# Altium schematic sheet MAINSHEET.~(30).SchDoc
size 594 x 420 mm; Scale: 1:1; Разраб.: Иванов; Обозначение документа: АБВГ.123456.001 Э3; Пров.: Петров; Утв.: Сидоров; Наименование организации: ОАО "Концерн "МПО-Гидроприбор"; Перв. применение: АБВГ.123456.000; Наименование изделия 1: Плата; Наименование изделия 2: Схема электрическая; Наименование изделия 3: принципиальная; Нач. отд.: Нач. отд.; Фамилия нач. отд.: Сидоров
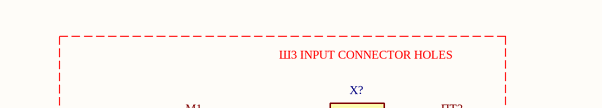
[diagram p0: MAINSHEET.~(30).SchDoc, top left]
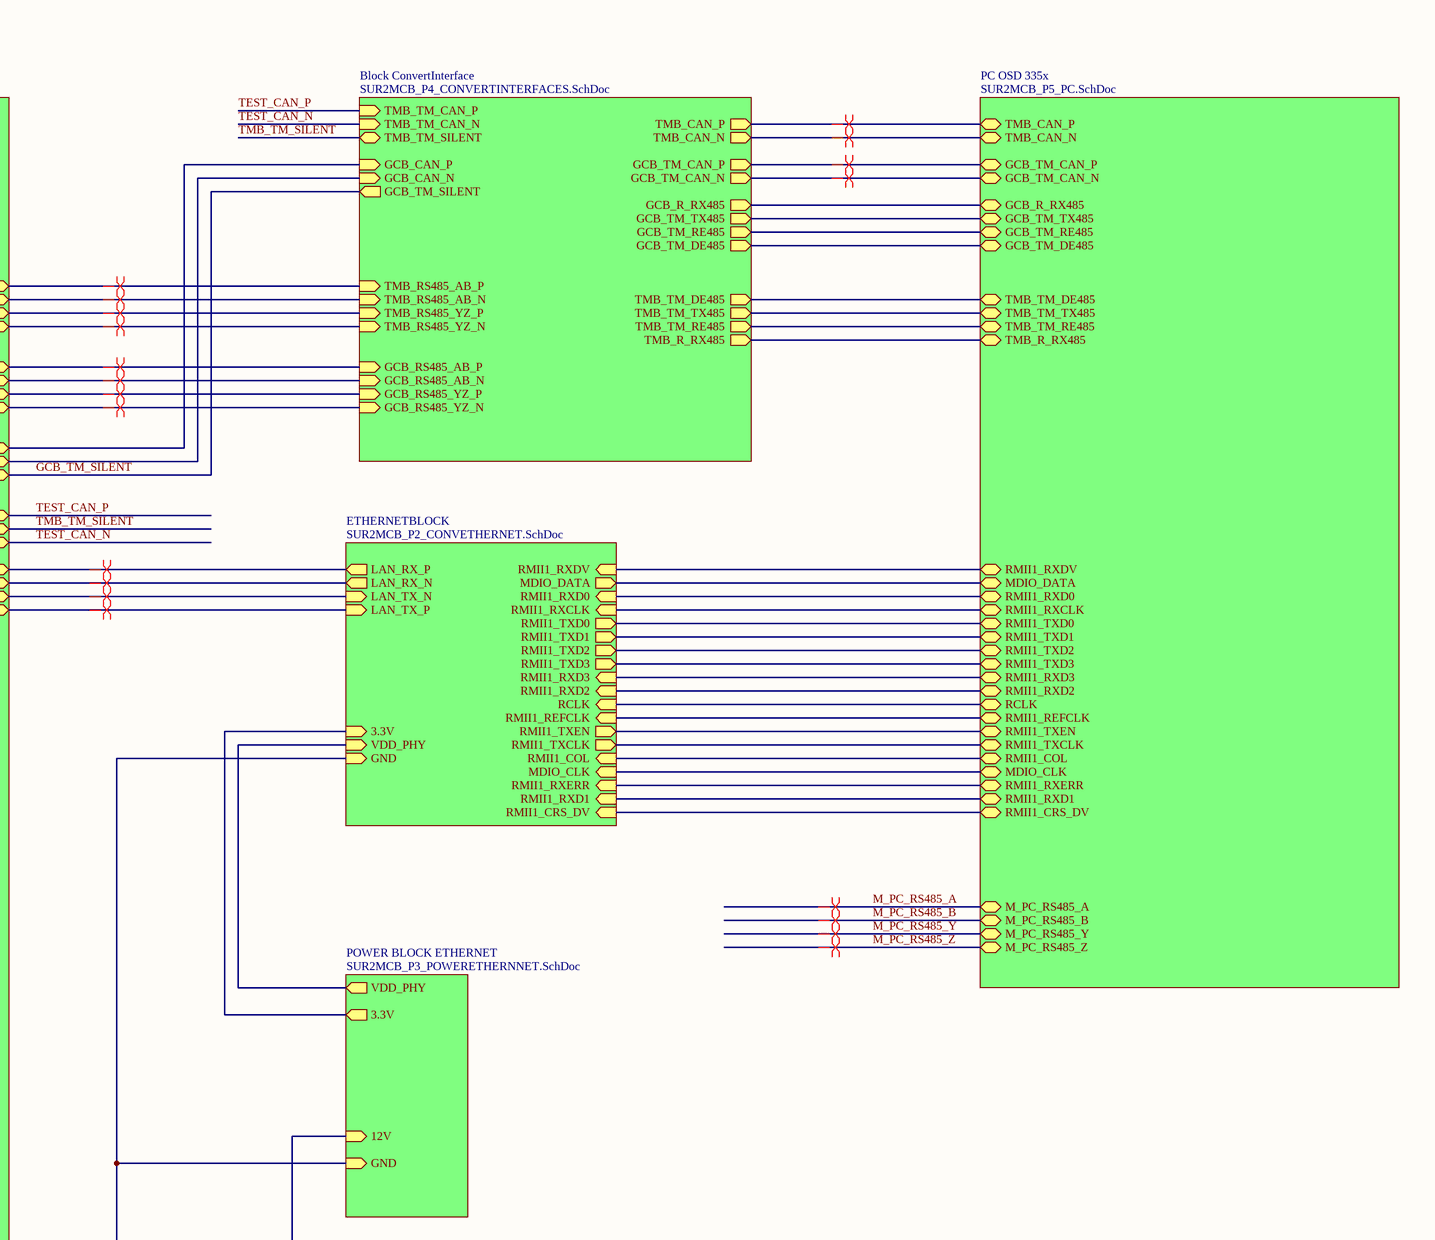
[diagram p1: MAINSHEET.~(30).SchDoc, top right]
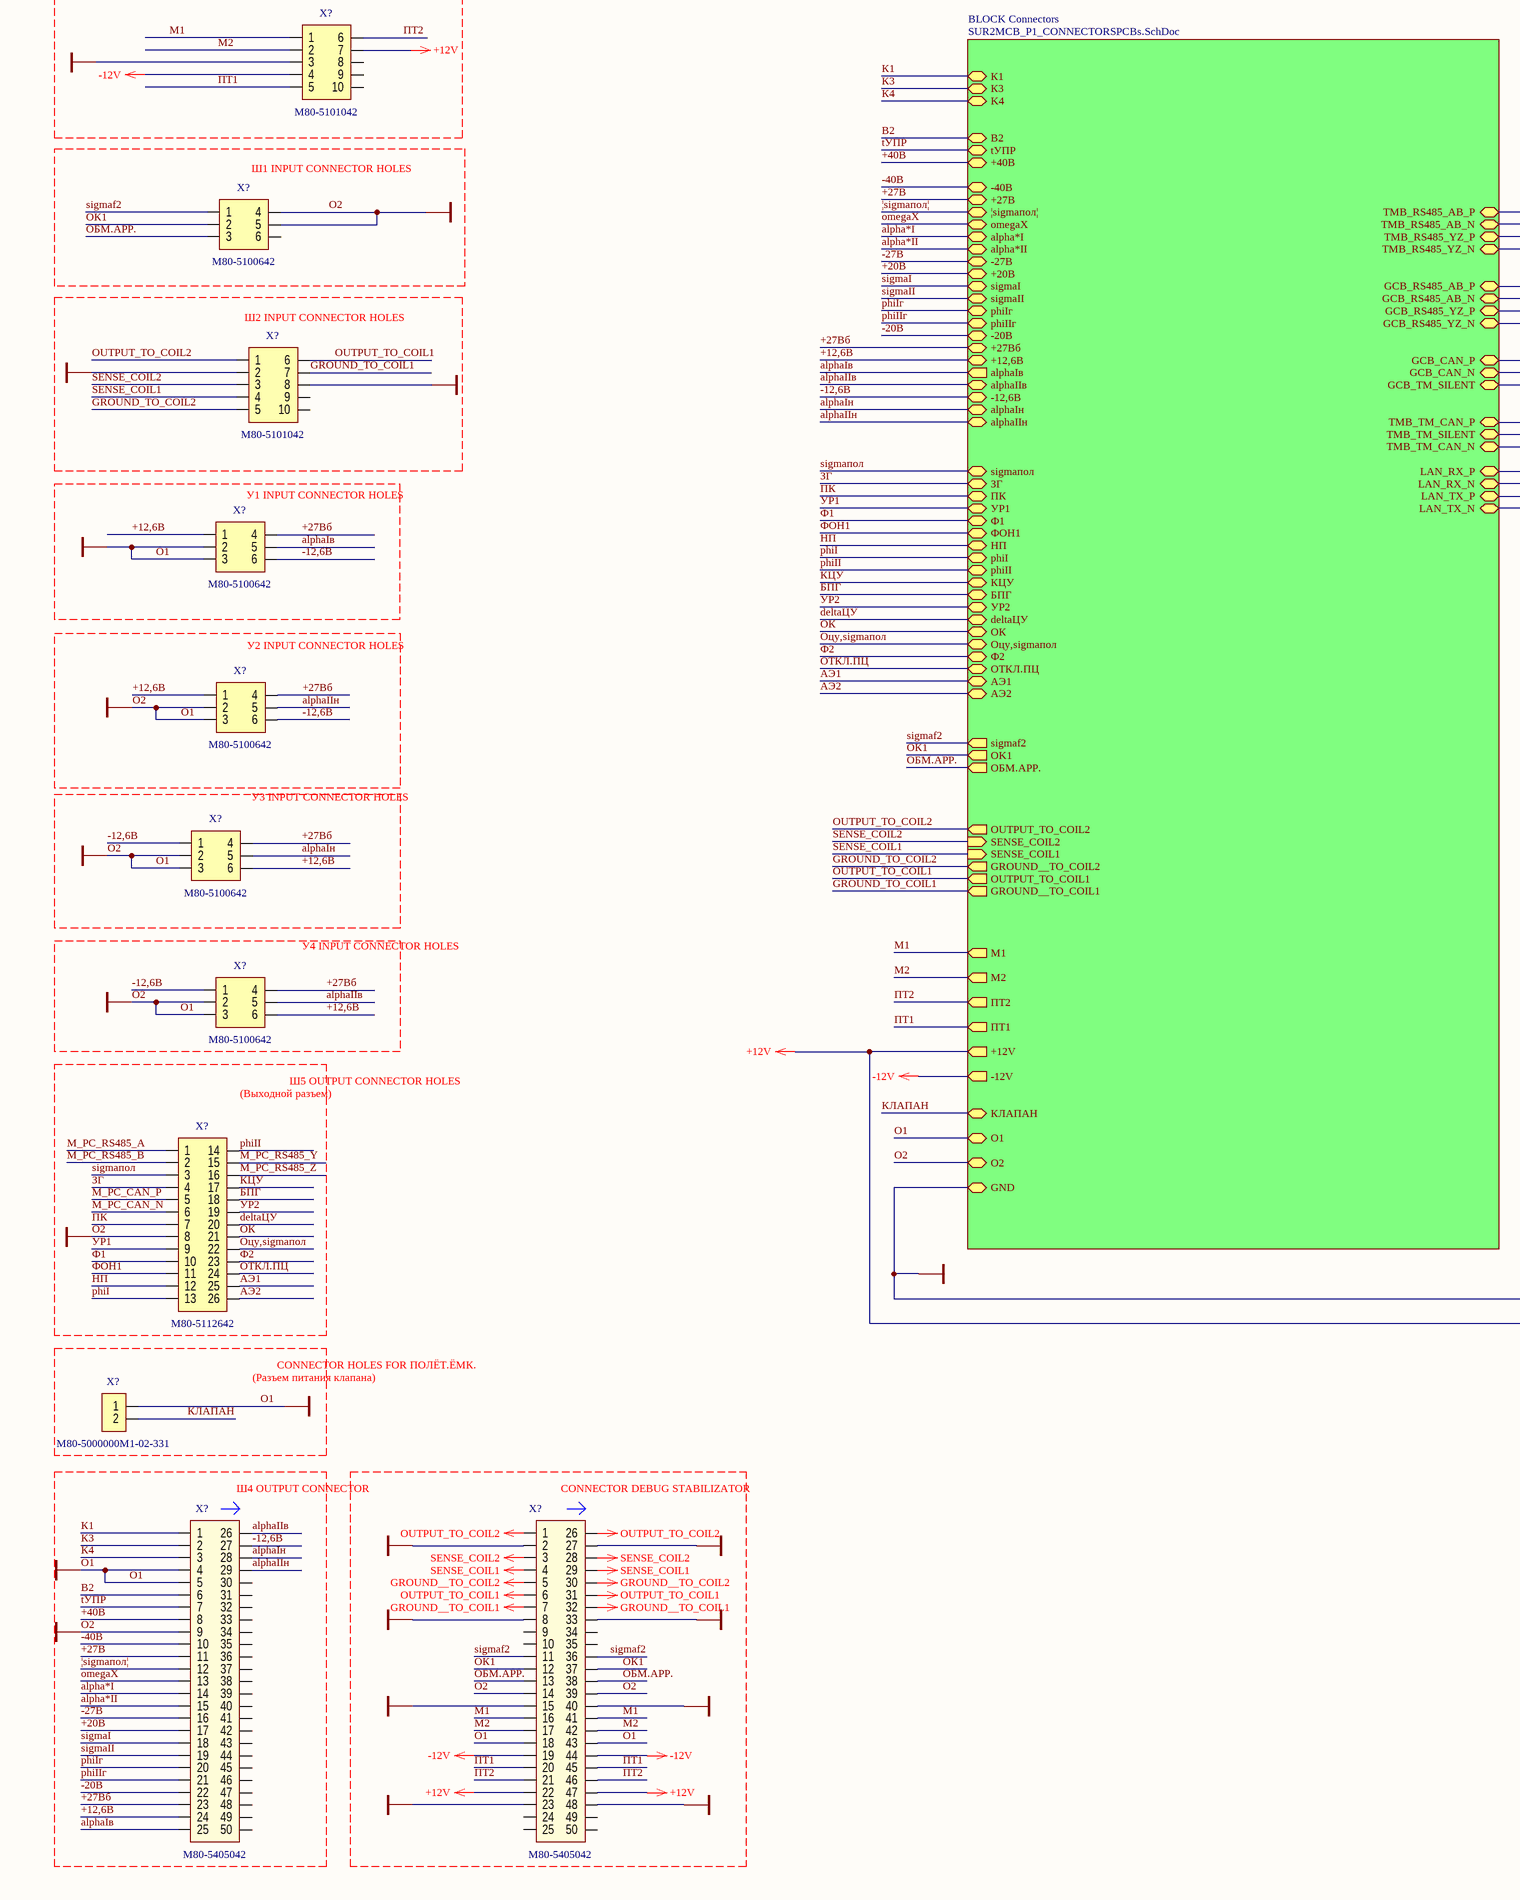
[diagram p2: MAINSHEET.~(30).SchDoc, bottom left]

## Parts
(Parts that share a designator on the sheet are numbered #1, #2 ... from top to bottom, then left to right.)
X?#1  value M80-5101042  [M80-5101042]
X?#2  value M80-5100642  [M80-5100642]
X?#3  value M80-5101042  [M80-5101042]
X?#4  value M80-5100642  [M80-5100642]
X?#5  value M80-5100642  [M80-5100642]
X?#6  value M80-5100642  [M80-5100642]
X?#7  value M80-5100642  [M80-5100642]
X?#8  value M80-5112642  [M80-5112642_HOR]
X?#9  value M80-5000000M1-02-331  [M80-5000000M1-02-331]
X?#10  value M80-5405042  [M80-5405042]
X?#11  value M80-5405042  [M80-5405042]

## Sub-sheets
BLOCK Connectors = SUR2MCB_P1_CONNECTORSPCBs.SchDoc: tУПР (bidir), B2 (bidir), K4 (bidir), +40В (bidir), К1 (bidir), К3 (bidir), OUTPUT_TO_COIL2 (out), OUTPUT_TO_COIL1 (out), GROUND__TO_COIL1 (out), SENSE_COIL2 (in), GROUND__TO_COIL2 (out), SENSE_COIL1 (in), M1 (out), КЛАПАН (bidir), О1 (bidir), O2 (bidir), TMB_RS485_AB_N (bidir), TMB_RS485_AB_P (bidir), TMB_RS485_YZ_N (bidir), TMB_RS485_YZ_P (bidir), LAN_RX_P (bidir), LAN_RX_N (bidir), LAN_TX_P (bidir), LAN_TX_N (bidir), GCB_RS485_AB_N (bidir), GCB_RS485_YZ_N (bidir), GCB_RS485_YZ_P (bidir), GCB_RS485_AB_P (bidir), GCB_CAN_P (bidir), GCB_CAN_N (bidir), GCB_TM_SILENT (bidir), TMB_TM_CAN_P (bidir), TMB_TM_SILENT (bidir), TMB_TM_CAN_N (bidir), -40В (bidir), +27В (bidir), ¦sigmaпол¦ (bidir), omegaX (bidir), alpha*II (bidir), alpha*I (bidir), -27В (bidir), +20В (bidir), -20В (bidir), sigmaII (bidir), sigmaI (bidir), phiIIг (bidir), phiIг (bidir), +27Вб (bidir), +12,6В (bidir), -12,6В (bidir), alphaIв (out), alphaIIв (bidir), alphaIIн (bidir), alphaIн (bidir), sigmaпол (bidir), ЗГ (bidir), ПК (bidir), УР1 (bidir), Ф1 (bidir), ФОН1 (bidir), НП (bidir), phiI (bidir), phiII (bidir), ПТ2 (out), +12V (out), КЦУ (bidir), БПГ (bidir), УР2 (bidir), deltaЦУ (bidir), ОК (bidir), Оцу,sigmaпол (bidir), Ф2 (bidir), ОТКЛ.ПЦ (bidir), АЭ1 (bidir), АЭ2 (bidir), ПТ1 (out), M2 (out), -12V (out), sigmaf2 (out), OK1 (out), ОБМ.АРР. (out), GND (bidir)
Block ConvertInterface = SUR2MCB_P4_CONVERTINTERFACES.SchDoc: TMB_TM_TX485 (out), GCB_RS485_YZ_P (in), TMB_R_RX485 (out), GCB_RS485_YZ_N (in), GCB_RS485_AB_P (in), TMB_TM_RE485 (out), GCB_TM_CAN_P (out), TMB_TM_DE485 (out), GCB_TM_CAN_N (out), GCB_RS485_AB_N (in), TMB_RS485_YZ_N (in), GCB_TM_RE485 (out), GCB_CAN_P (in), GCB_R_RX485 (out), GCB_TM_TX485 (out), TMB_RS485_AB_P (in), GCB_TM_SILENT (out), GCB_CAN_N (in), TMB_RS485_YZ_P (in), TMB_RS485_AB_N (in), GCB_TM_DE485 (out), TMB_TM_SILENT (bidir), TMB_TM_CAN_P (in), TMB_TM_CAN_N (in), TMB_CAN_P (out), TMB_CAN_N (out)
ETHERNETBLOCK = SUR2MCB_P2_CONVETHERNET.SchDoc: RMII1_RXDV (in), MDIO_DATA (out), RMII1_RXD0 (in), RMII1_RXCLK (in), RMII1_TXD0 (out), RMII1_TXD2 (out), RMII1_TXD3 (out), RMII1_RXD3 (in), RMII1_RXD2 (in), LAN_RX_P (out), RCLK (in), LAN_RX_N (out), LAN_TX_N (in), RMII1_REFCLK (in), RMII1_TXEN (out), LAN_TX_P (in), RMII1_TXCLK (out), RMII1_COL (in), MDIO_CLK (in), RMII1_TXD1 (out), GND (in), VDD_PHY (in), 3.3V (in), RMII1_RXERR (in), RMII1_RXD1 (in), RMII1_CRS_DV (in)
PC OSD 335x = SUR2MCB_P5_PC.SchDoc: GCB_R_RX485 (bidir), GCB_TM_CAN_N (bidir), GCB_TM_RE485 (bidir), GCB_TM_TX485 (bidir), TMB_TM_DE485 (bidir), GCB_TM_DE485 (bidir), TMB_TM_RE485 (bidir), TMB_TM_TX485 (bidir), TMB_R_RX485 (bidir), RMII1_TXCLK (bidir), GCB_TM_CAN_P (bidir), TMB_CAN_N (bidir), TMB_CAN_P (bidir), RMII1_TXD0 (bidir), RMII1_CRS_DV (bidir), RMII1_TXD2 (bidir), MDIO_CLK (bidir), RMII1_RXDV (bidir), RMII1_TXD1 (bidir), RMII1_TXEN (bidir), RMII1_RXD3 (bidir), RMII1_RXERR (bidir), RMII1_TXD3 (bidir), RMII1_RXD0 (bidir), MDIO_DATA (bidir), RMII1_RXD2 (bidir), RMII1_RXD1 (bidir), RMII1_COL (bidir), RMII1_RXCLK (bidir), RMII1_REFCLK (bidir), RCLK (bidir), M_PC_RS485_Z (bidir), M_PC_RS485_Y (bidir), M_PC_RS485_B (bidir), M_PC_RS485_A (bidir)
POWER BLOCK ETHERNET = SUR2MCB_P3_POWERETHERNNET.SchDoc: 12V (in), VDD_PHY (out), 3.3V (out), GND (in)

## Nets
+12V: X?#1.7 X?#11.22 X?#11.47 ; sheet BLOCK Connectors/+12V, sheet POWER BLOCK ETHERNET/12V
-12V: X?#1.4 X?#11.19 X?#11.44 ; sheet BLOCK Connectors/-12V
GROUND__TO_COIL1: X?#11.7 X?#11.32
GROUND__TO_COIL2: X?#11.5 X?#11.30
OUTPUT_TO_COIL1: X?#3.6 X?#11.6 X?#11.31 ; sheet BLOCK Connectors/OUTPUT_TO_COIL1
OUTPUT_TO_COIL2: X?#3.1 X?#11.1 X?#11.26 ; sheet BLOCK Connectors/OUTPUT_TO_COIL2
SENSE_COIL1: X?#3.4 X?#11.4 X?#11.29 ; sheet BLOCK Connectors/SENSE_COIL1
SENSE_COIL2: X?#3.3 X?#11.3 X?#11.28 ; sheet BLOCK Connectors/SENSE_COIL2
О1: X?#1.3 X?#2.4 X?#2.5 X?#3.2 X?#3.8 X?#4.2 X?#4.3 X?#5.2 X?#5.3 X?#6.2 X?#6.3 X?#7.2 X?#7.3 X?#8.8 X?#9.1 X?#10.4 X?#10.5 X?#10.9 X?#11.2 X?#11.8 X?#11.14 X?#11.15 X?#11.18 X?#11.23 X?#11.27 X?#11.33 X?#11.39 X?#11.40 X?#11.43 X?#11.48 ; sheet BLOCK Connectors/О1, sheet BLOCK Connectors/O2, sheet BLOCK Connectors/GND, sheet ETHERNETBLOCK/GND, sheet POWER BLOCK ETHERNET/GND  [also labelled GND, О2]
+12,6В: X?#4.1 X?#5.1 X?#6.6 X?#7.6 X?#10.24 ; sheet BLOCK Connectors/+12,6В
+20В: X?#10.17 ; sheet BLOCK Connectors/+20В
+27В: X?#10.11 ; sheet BLOCK Connectors/+27В
+27Вб: X?#4.4 X?#5.4 X?#6.4 X?#7.4 X?#10.23 ; sheet BLOCK Connectors/+27Вб
+40В: X?#10.8 ; sheet BLOCK Connectors/+40В
-12,6В: X?#4.6 X?#5.6 X?#6.1 X?#7.1 X?#10.27 ; sheet BLOCK Connectors/-12,6В
-20В: X?#10.22 ; sheet BLOCK Connectors/-20В
-27В: X?#10.16 ; sheet BLOCK Connectors/-27В
-40В: X?#10.10 ; sheet BLOCK Connectors/-40В
alpha*I: X?#10.14 ; sheet BLOCK Connectors/alpha*I
alpha*II: X?#10.15 ; sheet BLOCK Connectors/alpha*II
alphaIIв: X?#7.5 X?#10.26 ; sheet BLOCK Connectors/alphaIIв
alphaIIн: X?#5.5 X?#10.29 ; sheet BLOCK Connectors/alphaIIн
alphaIв: X?#4.5 X?#10.25 ; sheet BLOCK Connectors/alphaIв
alphaIн: X?#6.5 X?#10.28 ; sheet BLOCK Connectors/alphaIн
deltaЦУ: X?#8.20 ; sheet BLOCK Connectors/deltaЦУ
GCB_TM_SILENT: sheet BLOCK Connectors/GCB_TM_SILENT, sheet Block ConvertInterface/GCB_TM_SILENT
GROUND_TO_COIL1: X?#3.7 ; sheet BLOCK Connectors/GROUND__TO_COIL1
GROUND_TO_COIL2: X?#3.5 ; sheet BLOCK Connectors/GROUND__TO_COIL2
M_PC_CAN_N: X?#8.6
M_PC_CAN_P: X?#8.5
M_PC_RS485_A: X?#8.1 ; sheet PC OSD 335x/M_PC_RS485_A
M_PC_RS485_B: X?#8.2 ; sheet PC OSD 335x/M_PC_RS485_B
M_PC_RS485_Y: X?#8.15 ; sheet PC OSD 335x/M_PC_RS485_Y
M_PC_RS485_Z: X?#8.16 ; sheet PC OSD 335x/M_PC_RS485_Z
omegaX: X?#10.13 ; sheet BLOCK Connectors/omegaX
phiI: X?#8.13 ; sheet BLOCK Connectors/phiI
phiII: X?#8.14 ; sheet BLOCK Connectors/phiII
phiIIг: X?#10.21 ; sheet BLOCK Connectors/phiIIг
phiIг: X?#10.20 ; sheet BLOCK Connectors/phiIг
sigmaf2: X?#2.1 X?#11.11 X?#11.36 ; sheet BLOCK Connectors/sigmaf2
sigmaI: X?#10.18 ; sheet BLOCK Connectors/sigmaI
sigmaII: X?#10.19 ; sheet BLOCK Connectors/sigmaII
sigmaпол: X?#8.3 ; sheet BLOCK Connectors/sigmaпол
TEST_CAN_N: sheet BLOCK Connectors/TMB_TM_CAN_N, sheet Block ConvertInterface/TMB_TM_CAN_N
TEST_CAN_P: sheet BLOCK Connectors/TMB_TM_CAN_P, sheet Block ConvertInterface/TMB_TM_CAN_P
TMB_TM_SILENT: sheet BLOCK Connectors/TMB_TM_SILENT, sheet Block ConvertInterface/TMB_TM_SILENT
tУПР: X?#10.7 ; sheet BLOCK Connectors/tУПР
¦sigmaпол¦: X?#10.12 ; sheet BLOCK Connectors/¦sigmaпол¦
АЭ1: X?#8.25 ; sheet BLOCK Connectors/АЭ1
АЭ2: X?#8.26 ; sheet BLOCK Connectors/АЭ2
БПГ: X?#8.18 ; sheet BLOCK Connectors/БПГ
В2: X?#10.6 ; sheet BLOCK Connectors/B2
ЗГ: X?#8.4 ; sheet BLOCK Connectors/ЗГ
К1: X?#10.1 ; sheet BLOCK Connectors/К1
К3: X?#10.2 ; sheet BLOCK Connectors/К3
К4: X?#10.3 ; sheet BLOCK Connectors/K4
КЛАПАН: X?#9.2 ; sheet BLOCK Connectors/КЛАПАН
КЦУ: X?#8.17 ; sheet BLOCK Connectors/КЦУ
М1: X?#1.1 X?#11.16 X?#11.41 ; sheet BLOCK Connectors/M1
М2: X?#1.2 X?#11.17 X?#11.42 ; sheet BLOCK Connectors/M2
НП: X?#8.12 ; sheet BLOCK Connectors/НП
ОБМ.АРР.: X?#2.3 X?#11.13 X?#11.38 ; sheet BLOCK Connectors/ОБМ.АРР.
ОК: X?#8.21 ; sheet BLOCK Connectors/ОК
ОК1: X?#2.2 X?#11.12 X?#11.37 ; sheet BLOCK Connectors/OK1
ОТКЛ.ПЦ: X?#8.24 ; sheet BLOCK Connectors/ОТКЛ.ПЦ
Оцу,sigmaпол: X?#8.22 ; sheet BLOCK Connectors/Оцу,sigmaпол
ПК: X?#8.7 ; sheet BLOCK Connectors/ПК
ПТ1: X?#1.5 X?#11.20 X?#11.45 ; sheet BLOCK Connectors/ПТ1
ПТ2: X?#1.6 X?#11.21 X?#11.46 ; sheet BLOCK Connectors/ПТ2
УР1: X?#8.9 ; sheet BLOCK Connectors/УР1
УР2: X?#8.19 ; sheet BLOCK Connectors/УР2
Ф1: X?#8.10 ; sheet BLOCK Connectors/Ф1
Ф2: X?#8.23 ; sheet BLOCK Connectors/Ф2
ФОН1: X?#8.11 ; sheet BLOCK Connectors/ФОН1
(unnamed): sheet BLOCK Connectors/TMB_RS485_AB_N, sheet Block ConvertInterface/TMB_RS485_AB_N
(unnamed): sheet BLOCK Connectors/TMB_RS485_AB_P, sheet Block ConvertInterface/TMB_RS485_AB_P  [a separate net that carries the same name]
(unnamed): sheet BLOCK Connectors/TMB_RS485_YZ_N, sheet Block ConvertInterface/TMB_RS485_YZ_N  [a separate net that carries the same name]
(unnamed): sheet BLOCK Connectors/TMB_RS485_YZ_P, sheet Block ConvertInterface/TMB_RS485_YZ_P  [a separate net that carries the same name]
(unnamed): sheet BLOCK Connectors/LAN_RX_P, sheet ETHERNETBLOCK/LAN_RX_P  [a separate net that carries the same name]
(unnamed): sheet BLOCK Connectors/LAN_RX_N, sheet ETHERNETBLOCK/LAN_RX_N  [a separate net that carries the same name]
(unnamed): sheet BLOCK Connectors/LAN_TX_P, sheet ETHERNETBLOCK/LAN_TX_N  [a separate net that carries the same name]
(unnamed): sheet BLOCK Connectors/LAN_TX_N, sheet ETHERNETBLOCK/LAN_TX_P  [a separate net that carries the same name]
(unnamed): sheet BLOCK Connectors/GCB_RS485_AB_N, sheet Block ConvertInterface/GCB_RS485_AB_N  [a separate net that carries the same name]
(unnamed): sheet BLOCK Connectors/GCB_RS485_YZ_N, sheet Block ConvertInterface/GCB_RS485_YZ_N  [a separate net that carries the same name]
(unnamed): sheet BLOCK Connectors/GCB_RS485_YZ_P, sheet Block ConvertInterface/GCB_RS485_YZ_P  [a separate net that carries the same name]
(unnamed): sheet BLOCK Connectors/GCB_RS485_AB_P, sheet Block ConvertInterface/GCB_RS485_AB_P  [a separate net that carries the same name]
(unnamed): sheet BLOCK Connectors/GCB_CAN_P, sheet Block ConvertInterface/GCB_CAN_P  [a separate net that carries the same name]
(unnamed): sheet BLOCK Connectors/GCB_CAN_N, sheet Block ConvertInterface/GCB_CAN_N  [a separate net that carries the same name]
(unnamed): sheet ETHERNETBLOCK/RMII1_RXDV, sheet PC OSD 335x/RMII1_RXDV  [a separate net that carries the same name]
(unnamed): sheet ETHERNETBLOCK/MDIO_DATA, sheet PC OSD 335x/MDIO_DATA  [a separate net that carries the same name]
(unnamed): sheet ETHERNETBLOCK/RMII1_RXD0, sheet PC OSD 335x/RMII1_RXD0  [a separate net that carries the same name]
(unnamed): sheet ETHERNETBLOCK/RMII1_RXCLK, sheet PC OSD 335x/RMII1_RXCLK  [a separate net that carries the same name]
(unnamed): sheet ETHERNETBLOCK/RMII1_TXD0, sheet PC OSD 335x/RMII1_TXD0  [a separate net that carries the same name]
(unnamed): sheet ETHERNETBLOCK/RMII1_TXD2, sheet PC OSD 335x/RMII1_TXD2  [a separate net that carries the same name]
(unnamed): sheet ETHERNETBLOCK/RMII1_TXD3, sheet PC OSD 335x/RMII1_TXD3  [a separate net that carries the same name]
(unnamed): sheet ETHERNETBLOCK/RMII1_RXD3, sheet PC OSD 335x/RMII1_RXD3  [a separate net that carries the same name]
(unnamed): sheet ETHERNETBLOCK/RMII1_RXD2, sheet PC OSD 335x/RMII1_RXD2  [a separate net that carries the same name]
(unnamed): sheet ETHERNETBLOCK/RCLK, sheet PC OSD 335x/RCLK  [a separate net that carries the same name]
(unnamed): sheet ETHERNETBLOCK/RMII1_REFCLK, sheet PC OSD 335x/RMII1_REFCLK  [a separate net that carries the same name]
(unnamed): sheet ETHERNETBLOCK/RMII1_TXEN, sheet PC OSD 335x/RMII1_TXEN  [a separate net that carries the same name]
(unnamed): sheet ETHERNETBLOCK/RMII1_TXCLK, sheet PC OSD 335x/RMII1_TXCLK  [a separate net that carries the same name]
(unnamed): sheet ETHERNETBLOCK/RMII1_COL, sheet PC OSD 335x/RMII1_COL  [a separate net that carries the same name]
(unnamed): sheet ETHERNETBLOCK/MDIO_CLK, sheet PC OSD 335x/MDIO_CLK  [a separate net that carries the same name]
(unnamed): sheet ETHERNETBLOCK/RMII1_TXD1, sheet PC OSD 335x/RMII1_TXD1  [a separate net that carries the same name]
(unnamed): sheet ETHERNETBLOCK/VDD_PHY, sheet POWER BLOCK ETHERNET/VDD_PHY  [a separate net that carries the same name]
(unnamed): sheet ETHERNETBLOCK/3.3V, sheet POWER BLOCK ETHERNET/3.3V  [a separate net that carries the same name]
(unnamed): sheet ETHERNETBLOCK/RMII1_RXERR, sheet PC OSD 335x/RMII1_RXERR  [a separate net that carries the same name]
(unnamed): sheet ETHERNETBLOCK/RMII1_RXD1, sheet PC OSD 335x/RMII1_RXD1  [a separate net that carries the same name]
(unnamed): sheet ETHERNETBLOCK/RMII1_CRS_DV, sheet PC OSD 335x/RMII1_CRS_DV  [a separate net that carries the same name]
(unnamed): sheet PC OSD 335x/GCB_R_RX485, sheet Block ConvertInterface/GCB_R_RX485  [a separate net that carries the same name]
(unnamed): sheet PC OSD 335x/GCB_TM_CAN_N, sheet Block ConvertInterface/GCB_TM_CAN_N  [a separate net that carries the same name]
(unnamed): sheet PC OSD 335x/GCB_TM_RE485, sheet Block ConvertInterface/GCB_TM_RE485  [a separate net that carries the same name]
(unnamed): sheet PC OSD 335x/GCB_TM_TX485, sheet Block ConvertInterface/GCB_TM_TX485  [a separate net that carries the same name]
(unnamed): sheet PC OSD 335x/TMB_TM_DE485, sheet Block ConvertInterface/TMB_TM_DE485  [a separate net that carries the same name]
(unnamed): sheet PC OSD 335x/GCB_TM_DE485, sheet Block ConvertInterface/GCB_TM_DE485  [a separate net that carries the same name]
(unnamed): sheet PC OSD 335x/TMB_TM_RE485, sheet Block ConvertInterface/TMB_TM_RE485  [a separate net that carries the same name]
(unnamed): sheet PC OSD 335x/TMB_TM_TX485, sheet Block ConvertInterface/TMB_TM_TX485  [a separate net that carries the same name]
(unnamed): sheet PC OSD 335x/TMB_R_RX485, sheet Block ConvertInterface/TMB_R_RX485  [a separate net that carries the same name]
(unnamed): sheet PC OSD 335x/GCB_TM_CAN_P, sheet Block ConvertInterface/GCB_TM_CAN_P  [a separate net that carries the same name]
(unnamed): sheet PC OSD 335x/TMB_CAN_N, sheet Block ConvertInterface/TMB_CAN_N  [a separate net that carries the same name]
(unnamed): sheet PC OSD 335x/TMB_CAN_P, sheet Block ConvertInterface/TMB_CAN_P  [a separate net that carries the same name]

Not connected (* = marked no-connect by the designer): X?#1 8 9 10; X?#2 6; X?#3 9 10; X?#10 30 31 32 33 34 35 36 37 38 39 40 41 42 43 44 45 46 47 48 49 50; X?#11 9 10 24 25 34 35 49 50

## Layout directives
differential pair: (no net found under the mark), M_PC_RS485_A, M_PC_RS485_B, M_PC_RS485_Y, M_PC_RS485_Z

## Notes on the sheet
- Ш3 INPUT CONNECTOR HOLES
- (near X?#2) Ш1 INPUT CONNECTOR HOLES
- (near X?#3) Ш2 INPUT CONNECTOR HOLES
- (near X?#4) У1 INPUT CONNECTOR HOLES
- (near X?#5) У2 INPUT CONNECTOR HOLES
- (near X?#6) У3 INPUT CONNECTOR HOLES
- (near X?#7) У4 INPUT CONNECTOR HOLES
- (Выходной разъем)
- Ш5 OUTPUT CONNECTOR HOLES
- (near X?#9) CONNECTOR HOLES FOR ПОЛЁТ.ЁМК.
- (near X?#9) (Разъем питания клапана)
- (near X?#10) Ш4 OUTPUT CONNECTOR
- (near X?#11) CONNECTOR DEBUG STABILIZATOR

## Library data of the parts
X?#1 X?#3 = M80-5101042: J-TEK 10 POS DIL MALE 2.0MM 2.2A 800V; ValueManufacturer: Harvin Inc.; PowerVoltage: 2.2A, 800V; ValueDescription: M80-5101042 Вилка Harvin Inc.  6.05x20.4mm  2.2A, 800V; ValueType: Connector
X?#2 X?#4-X?#7 = M80-5100642: J-TEK 6 POS DIL MALE 2.0MM 2.2A 800V; ValueManufacturer: Harvin Inc.; PowerVoltage: 2.2A, 800V; ValueDescription: M80-5100642 Вилка Harvin Inc.  6.05x16.4mm  2.2A, 800V; ValueType: Connector
X?#8 = M80-5112642_HOR: J-TEK 26 POS DIL MALE 2.0MM 2.2A 800V; ValueManufacturer: Harvin Inc.; PowerVoltage: 2.2A, 800V; ValueDescription: M80-5112642 Вилка Harvin Inc.  6.05x36mm  2.2A, 800V; ValueType: Connector
X?#9 = M80-5000000M1-02-331: MIX-TEK 2 POS DIL MALE 4.0MM 20A 600V; ValueManufacturer: Harvin Inc.; PowerVoltage: 20A, 600V; ValueDescription: M80-5000000M1-02-331 Вилка Harvin Inc.  6.05x18.4mm  20A, 600V; ValueType: Connector
X?#10 X?#11 = M80-5405042: CONN HDR 2MM R/A W/SCREW 50POS; ValueManufacturer: Harwin Inc.; PowerVoltage: 2.2A, 800V; TechSpec: 3A; ValueDescription: M80-5405042 Вилка Harwin Inc.  10x60mm  3A; ValueType: Male Socket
